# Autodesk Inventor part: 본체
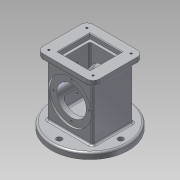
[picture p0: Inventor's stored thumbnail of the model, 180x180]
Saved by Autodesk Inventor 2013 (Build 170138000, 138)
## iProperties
Created: 2018-10
Part Number: 본체
Material: 알루미늄 6061
Document SubType Name: Modeling
Designer: Administrator
Density: 2.71 g/cm^3
Mass: 988.226 g
Surface Area: 743.905 cm^2
Volume: 364.659 cm^3
Author: Administrator
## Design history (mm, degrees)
sketch "스케치1"
  geometry: C1 r 62.5 at (0, 0); 1 further point
  constraints: 1 centre point, 1 coincident
  dimensions: "d0" = 125 diameter of C1
extrude "돌출1" new body sketch "스케치1" distance "d1" = 10; taper "d2" = 0 deg
sketch "스케치2"
  geometry: L1 (-37, -33)-(37, -33); L2 (37, -33)-(37, 33); L3 (37, 33)-(-37, 33); L4 (-37, 33)-(-37, -33); C1 r 62.5 at (0, 0) reference; 2 further points
  constraints: 8 end point, 2 midpoint, 2 parallel, 1 horizontal, 1 horizontal alignment, 1 perpendicular, 1 vertical alignment
  dimensions: "d3" = 74 distance of L3.end L2.end; "d4" = 66 distance of L2.end L1.end
extrude "돌출2" join sketch "스케치2" distance "d5" = 88; taper "d6" = 0 deg
sketch "스케치3"
  geometry: L1 (-46, -41)-(46, -41); L2 (46, -41)-(46, 41); L3 (46, 41)-(-46, 41); L4 (-46, 41)-(-46, -41); 3 further points
  constraints: 8 end point, 2 midpoint, 2 parallel, 1 horizontal, 1 horizontal alignment, 1 perpendicular, 1 vertical alignment
  dimensions: "d7" = 92 distance of L3.end L2.end; "d8" = 82 distance of L2.end L1.end
extrude "돌출3" join sketch "스케치3" distance "d9" = 10; taper "d10" = 0 deg
sketch "스케치4"
  geometry: L1 (-26, -26)-(26, -26); L2 (26, -26)-(26, 26); L3 (26, 26)-(-26, 26); L4 (-26, 26)-(-26, -26); 3 further points
  constraints: 8 end point, 2 midpoint, 2 parallel, 1 horizontal, 1 horizontal alignment, 1 perpendicular, 1 vertical alignment
  dimensions: "d11" = 52 distance of L3.end L2.end; "d12" = 52 distance of L2.end L1.end
extrude "돌출4" cut sketch "스케치4" distance "d13" = 8; taper "d14" = 0 deg
sketch "스케치5"
  geometry: L1 (-22, -22)-(22, -22); L2 (22, -22)-(22, 22); L3 (22, 22)-(-22, 22); L4 (-22, 22)-(-22, -22); L5 (-46, -41)-(46, -41) reference; L6 (-46, 41)-(-46, -41) reference; L7 (46, 41)-(-46, 41) reference; L8 (46, -41)-(46, 41) reference; L9 (-37, 33)-(-37, -33) reference; L10 (-37, -33)-(37, -33) reference; L11 (37, -33)-(37, 33) reference; L12 (37, 33)-(-37, 33) reference; 3 further points
  constraints: 8 end point, 2 midpoint, 2 parallel, 1 horizontal, 1 horizontal alignment, 1 perpendicular, 1 vertical alignment
  dimensions: "d15" = 44 distance of L2.end L3.end; "d17" = 44 distance of L3.end L1.start
extrude "돌출5" cut sketch "스케치5" distance "d18" = 74; taper "d19" = 0 deg
sketch "스케치6"
  geometry: C1 r 62.5 at (0, 0) reference; C2 r 28 at (0, 0)
  constraints: 1 centre point, 1 coincident
  dimensions: "d20" = 56 diameter of C2
extrude "돌출6" cut sketch "스케치6" distance "d21" = 18; taper "d22" = -10 deg
sketch "스케치8"
  geometry: L1 (-25.5, -10)-(99.5, -10) reference; C1 r 35 at (37, 44); 2 further points
  constraints: 1 centre point, 1 midpoint, 1 vertical alignment
  dimensions: "d25" = 70 diameter of C1; "d26" = 54 distance from line of L1 C1.centre
extrude "돌출7" cut sketch "스케치8" distance "d27" = 3; taper "d28" = 0 deg
sketch "스케치9"
  geometry: C1 r 35 at (0, 0) reference; C2 r 24 at (0, 0); 1 further point
  constraints: 1 centre point, 1 coincident
  dimensions: "d29" = 48 diameter of C2
extrude "돌출8" cut sketch "스케치9" stored distance "d30" = 3; taper "d31" = 0 deg
sketch "스케치10"
  geometry: C1 r 24 at (0, 0) reference; 2 further points
  constraints: 1 vertical alignment
  dimensions: "d32" = 29 distance of point (0, 29) C1.centre
hole "구멍1" sketch "스케치10" at (0, 29) diameter "d33" = 3.242; stored, may be unused: countersink angle "d37" = 90 deg, drill point angle "d39" = 118 deg; dims "d34" = 4, "d35" = 4, "d36" = 2, "d38" = 6
sketch "스케치11"
  geometry: C1 r 62.5 at (0, 0) reference; C2 r 4.5 at (-50, 0)
  constraints: 1 centre point
  dimensions: "d43" = 50 distance of C2.centre C1.centre; "d44" = 9 diameter of C2
extrude "돌출9" cut sketch "스케치11" stored distance "d45" = 3; taper "d46" = 0 deg
sketch "스케치13"
  geometry: L1 (46, 41)-(-46, 41) reference; L2 (-46, 41)-(-46, -41) reference; 2 further points
  dimensions: "d98" = 10 distance from line of L1 point (-36, 31); "d99" = 10 distance from line of L2 point (-36, 31)
hole "구멍3" sketch "스케치13" at (-36, 31) diameter "d61" = 3.242; stored, may be unused: countersink angle "d65" = 90 deg, drill point angle "d67" = 118 deg; dims "d62" = 4, "d63" = 4, "d64" = 2, "d66" = 6
fillet "모깎기1" dims "d74" = 10
fillet "모깎기2" dims "d75" = 3
fillet "모깎기3" dims "d76" = 3
fillet "모깎기4" dims "d77" = 3
fillet "모깎기5" dims "d78" = 3
fillet "모깎기6" dims "d79" = 3
fillet "모깎기7" dims "d80" = 3
sketch "스케치14"
  geometry: L1 (72, 0)-(0, 0) reference; L2 (82, 0)-(82, 7) reference; 2 further points
  constraints: 1 other
  dimensions: "d81" = 4 distance from line of L1 point (36, 4); "d82" = 46 distance from line of point (36, 4) L2
feature "엠보싱1" sketch "스케치14" dims "d1" = 10, "d83" = 0.5, "d84" = 0
sketch "스케치15"
  geometry: L1 (-95, 92.5)-(-95, -32.5) reference; 4 further points
  constraints: 2 horizontal alignment, 1 midpoint
  dimensions: "d85" = 43 distance of point (-15, 30) point (-58, 30); "d87" = 37 distance from line of point (-58, 30) L1
hole "구멍4" sketch "스케치15" at (-15, 30), (-58, 30) diameter "d88" = 4.134; stored, may be unused: countersink angle "d92" = 90 deg, drill point angle "d94" = 118 deg; dims "d89" = 20, "d90" = 4, "d91" = 2, "d93" = 20
chamfer "모따기1" distance "d95" = 1; stored, may be unused: second distance "d96" = 2, angle "d97" = 45 deg
node "솔리드1"
mirror "대칭1"
pattern_circular "원형 패턴1" dims angle "d41" = 360 deg
mirror "대칭2"
pattern_circular "원형 패턴2" dims angle "d48" = 360 deg
pattern_linear "직사각형 패턴1" dims "d70" = 72, "d73" = 62
node "투영된 루프1"
